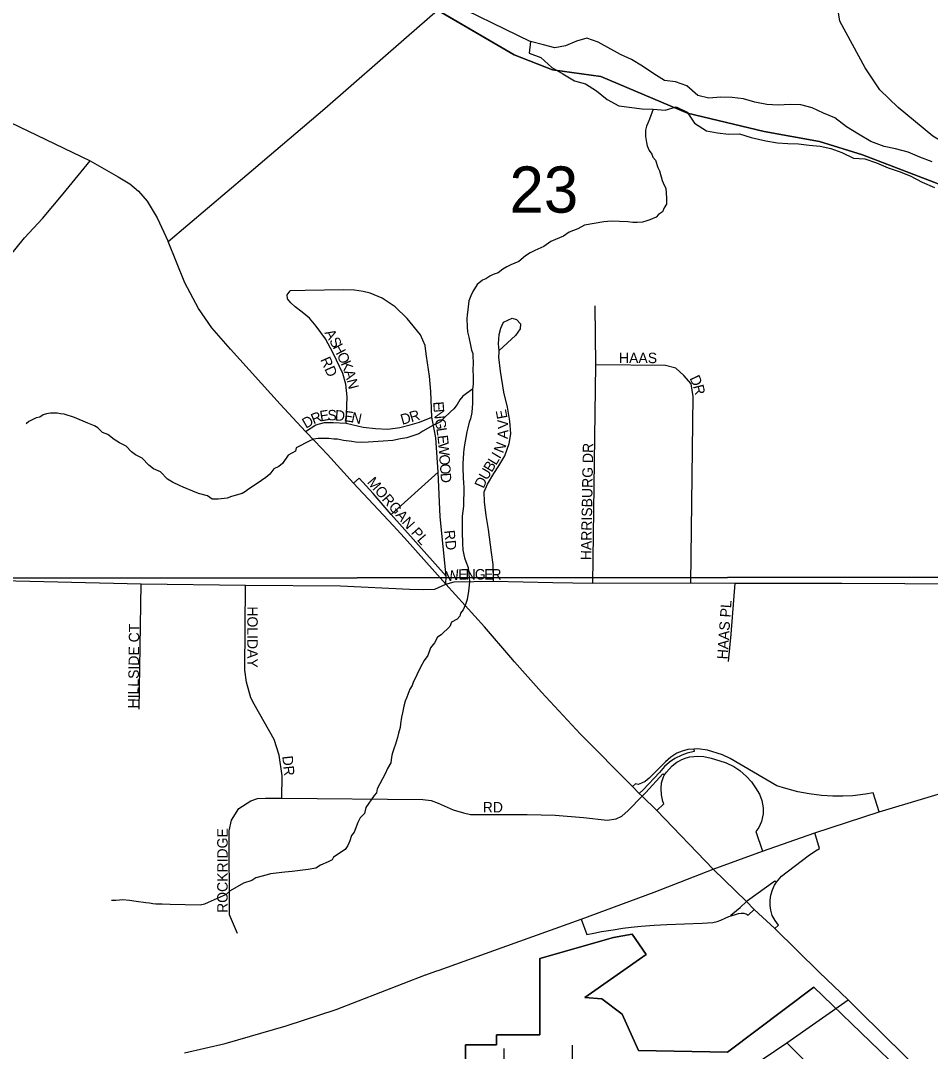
# Model space of a CAD drawing. Extents: x -209 to 4852, y 0 to 905.
# Drawn here: x 367.31 to 383.78, y 269.97 to 288.63 of the extents above; entities that cross this region are included whole.
import ezdxf

# ---------------------------------------------------------------- set-up
doc = ezdxf.new("R2010")
doc.units = 0
for name, color, linetype in [('GM_X_Airport_Location_Class_2', 7, 'Continuous'), ('GM_X_Airport_Location_Class_3', 7, 'Continuous'), ('GM_X_Corporation', 7, 'Continuous'), ('GM_X_County_Road', 7, 'Continuous'), ('GM_X_County_ROW', 7, 'Continuous'), ('GM_X_County_Subdivision_Text', 7, 'Continuous'), ('GM_X_Major_Lake', 7, 'Continuous'), ('GM_X_Minor_Lake_Text', 7, 'Continuous'), ('GM_X_Minor_River', 7, 'Continuous'), ('GM_X_Rail_Line', 7, 'Continuous'), ('GM_X_Rail_Line_Text', 7, 'Continuous'), ('GM_X_Township_Road_Text', 7, 'Continuous'), ('GM_X_US_Location', 7, 'Continuous')]:
    doc.layers.add(name, color=color, linetype=linetype)

msp = doc.modelspace()

# ---------------------------------------------------------------- linework, layer by layer
at = {"layer": 'GM_X_Airport_Location_Class_2'}
for points in [[(367.041, 284.247), (367.104, 284.359), (367.379, 284.704), (367.703, 285.054), (368.078, 285.498), (368.57, 286.095)], [(373.206, 281.346), (373.224, 281.827), (373.199, 282.052), (373.143, 282.249), (372.971, 282.617), (372.831, 282.877), (372.659, 283.101), (372.54, 283.251), (372.409, 283.355), (372.281, 283.455), (372.203, 283.523), (372.142, 283.596), (372.134, 283.67), (372.187, 283.742)], [(374.639, 282.698), (374.632, 282.752), (374.547, 282.944), (374.311, 283.242), (374.091, 283.451), (373.854, 283.608), (373.641, 283.698), (373.51, 283.731), (373.357, 283.753), (373.162, 283.759), (372.459, 283.748), (372.187, 283.742)], [(377.668, 278.453), (377.723, 282.403), (377.711, 283.474)], [(375.972, 282.633), (375.973, 282.663), (375.961, 282.784), (375.973, 282.953), (376.002, 283.069), (376.055, 283.175), (376.211, 283.25), (376.286, 283.225), (376.361, 283.147), (376.355, 283.056), (376.27, 282.934), (375.973, 282.663)], [(375.009, 278.433), (375.017, 278.576), (374.903, 279.654), (374.869, 280.46), (374.825, 281.082), (374.776, 281.366), (374.757, 281.457), (374.735, 281.919), (374.71, 282.2), (374.658, 282.558), (374.639, 282.698)], [(375.871, 278.485), (375.864, 278.789), (375.833, 279.004), (375.78, 279.423), (375.739, 279.676), (375.708, 279.923), (375.705, 280.107), (375.764, 280.245), (375.88, 280.435), (375.967, 280.573), (376.077, 280.757), (376.155, 280.979), (376.183, 281.157), (376.17, 281.382), (376.123, 281.635), (376.058, 281.907), (375.998, 282.291), (375.967, 282.544), (375.972, 282.633)], [(379.445, 278.46), (379.488, 281.831), (379.451, 282.062), (379.317, 282.208), (379.171, 282.342), (378.989, 282.391), (377.723, 282.403)], [(372.469, 281.198), (372.656, 281.315), (372.811, 281.359), (372.971, 281.358), (373.206, 281.346), (373.512, 281.277), (373.737, 281.252), (373.956, 281.241), (374.174, 281.268), (374.365, 281.315), (374.53, 281.365), (374.757, 281.457)], [(375.017, 278.576), (374.813, 278.801), (374.019, 279.695), (373.69, 280.074), (373.437, 280.351), (373.337, 280.262)], [(374.019, 279.695), (374.869, 280.46)], [(366.714, 278.504), (366.718, 278.504), (369.489, 278.438), (371.38, 278.415), (373.101, 278.401), (374.348, 278.345), (374.601, 278.336), (374.807, 278.345), (375.009, 278.433)], [(369.457, 276.172), (369.489, 278.438)], [(372.036, 274.557), (372.046, 274.963), (371.992, 275.335), (371.897, 275.622), (371.539, 276.261), (371.48, 276.375), (371.401, 276.657), (371.369, 276.877), (371.38, 278.415)], [(375.009, 278.433), (375.162, 278.477), (375.871, 278.485), (376.948, 278.466)], [(376.948, 278.466), (377.668, 278.453), (379.445, 278.46), (380.246, 278.449), (380.409, 278.45), (380.991, 278.449), (382.181, 278.449), (384.461, 278.437), (385.708, 278.435), (386.478, 278.437)], [(380.129, 277.031), (380.176, 277.528), (380.246, 278.449)], [(371.238, 272.107), (371.093, 272.449), (371.085, 273.966), (371.128, 274.163), (371.26, 274.371), (371.478, 274.513), (371.598, 274.554), (371.741, 274.557), (372.036, 274.557), (374.595, 274.535), (374.742, 274.518), (374.868, 274.469), (375.141, 274.349), (375.327, 274.294), (375.453, 274.264), (376.481, 274.264), (376.986, 274.25), (377.503, 274.207), (377.93, 274.163), (378.094, 274.185), (378.195, 274.234), (378.312, 274.338), (378.564, 274.595)], [(376.058, 269.566), (377.306, 269.552), (378.494, 269.542), (378.988, 269.535), (379.179, 269.522), (379.661, 269.42), (380.115, 269.461), (380.21, 269.493), (380.327, 269.548), (381.186, 270.131), (382.291, 270.908)], [(376.058, 270.024), (376.058, 269.566), (376.043, 266.655), (376.039, 265.976)], [(377.3, 266.702), (377.306, 269.552), (377.3, 270.086)], [(381.186, 270.131), (382.001, 269.307), (382.577, 268.74)]]:
    msp.add_lwpolyline(points, dxfattribs=at)
at = {"layer": 'GM_X_Corporation'}
for points in [[(359.101, 295.92), (359.22, 295.726), (359.989, 294.559), (360.498, 293.749), (360.741, 293.376), (360.976, 293.005), (361.061, 292.879), (361.234, 292.661), (361.398, 292.456), (361.814, 292.009), (362.465, 291.319), (363.235, 290.501), (363.961, 289.719), (364.692, 288.915), (364.928, 288.634), (365.294, 288.254), (365.884, 287.631), (366.349, 287.246), (366.697, 287.014), (367.127, 286.793), (368.57, 286.095)], [(369.983, 284.636), (371.408, 285.845), (372.818, 287.046), (374.298, 288.338), (374.86, 288.826), (375.008, 288.954)], [(368.57, 286.095), (369.076, 285.808), (369.284, 285.682), (369.441, 285.55), (369.6, 285.369), (369.782, 285.065), (369.983, 284.636)]]:
    msp.add_lwpolyline(points, dxfattribs=at)
at = {"layer": 'GM_X_County_Road'}
for points in [[(378.764, 287.034), (378.696, 286.848), (378.665, 286.78), (378.641, 286.727), (378.624, 286.651), (378.622, 286.537), (378.643, 286.43), (378.657, 286.369), (378.693, 286.285), (378.738, 286.216), (378.759, 286.162), (378.804, 286.108), (378.847, 285.978), (378.876, 285.917), (378.926, 285.741), (378.963, 285.657), (378.992, 285.603), (379.004, 285.421), (379.002, 285.314), (378.963, 285.246), (378.931, 285.171), (378.862, 285.127), (378.815, 285.074), (378.701, 285.031), (378.647, 285.009), (378.571, 284.987), (378.472, 284.981), (378.396, 284.983), (378.305, 284.992), (378.002, 285.005), (377.872, 284.992), (377.522, 284.93), (377.399, 284.864), (377.239, 284.806), (377.139, 284.731), (376.993, 284.673), (376.909, 284.637), (376.786, 284.548), (376.618, 284.475), (376.534, 284.43), (376.449, 284.379), (376.333, 284.274), (376.188, 284.216), (376.111, 284.18), (376.042, 284.135), (375.957, 284.068), (375.866, 284.039), (375.805, 284.01), (375.735, 283.958), (375.674, 283.936), (375.574, 283.855), (375.496, 283.734), (375.464, 283.651), (375.424, 283.561), (375.406, 283.401), (375.397, 283.31), (375.388, 283.234), (375.393, 283.09), (375.399, 282.999), (375.427, 282.907), (375.462, 282.731), (375.476, 282.67), (375.498, 282.609), (375.497, 282.541), (375.503, 282.457), (375.5, 282.29), (375.506, 282.214), (375.503, 282.054), (375.494, 281.963), (375.49, 281.773), (375.489, 281.697), (375.487, 281.629), (375.478, 281.538), (375.453, 281.424), (375.429, 281.364), (375.405, 281.265), (375.388, 281.19), (375.371, 281.091), (375.346, 280.955), (375.337, 280.871), (375.328, 280.81), (375.317, 280.613), (375.316, 280.537), (375.32, 280.362), (375.326, 280.263), (375.332, 280.187), (375.326, 279.845), (375.307, 279.663), (375.302, 279.382), (375.313, 279.169), (375.318, 279.047), (375.346, 278.91), (375.368, 278.841), (375.411, 278.734), (375.431, 278.551), (375.437, 278.475), (375.427, 278.361), (375.419, 278.308), (375.393, 278.156), (375.369, 278.081)], [(375.494, 281.963), (375.317, 281.837), (375.262, 281.77), (375.215, 281.687), (375.153, 281.604), (375.091, 281.552), (374.975, 281.44), (374.913, 281.373), (374.775, 281.307), (374.591, 281.204), (374.522, 281.152), (374.354, 281.101), (374.301, 281.08), (374.186, 281.066), (374.049, 281.031), (373.874, 281.019), (373.601, 281.001), (373.487, 280.995), (373.373, 281.005), (373.305, 281.014), (373.153, 281.032), (373.048, 281.056), (372.979, 281.057), (372.888, 281.067), (372.699, 281.07), (372.615, 281.056), (372.546, 281.027), (372.301, 280.902), (372.284, 280.842), (372.154, 280.768), (372.053, 280.618), (371.983, 280.566), (371.891, 280.522), (371.821, 280.424), (371.752, 280.365), (371.59, 280.254), (371.437, 280.15), (371.383, 280.113), (371.321, 280.076), (371.13, 280.018), (371.046, 279.99), (370.887, 279.97), (370.78, 279.971), (370.69, 280.034), (370.532, 280.075), (370.426, 280.115), (370.253, 280.186), (370.2, 280.21), (370.057, 280.281), (369.967, 280.336), (369.841, 280.467), (369.712, 280.523), (369.63, 280.585), (369.511, 280.716), (369.391, 280.772), (369.316, 280.826), (369.219, 280.934), (369.099, 280.99), (369.001, 281.052), (368.889, 281.145), (368.791, 281.178), (368.709, 281.263), (368.649, 281.302), (368.528, 281.35), (368.287, 281.453), (368.098, 281.509), (368.03, 281.518), (367.97, 281.527), (367.848, 281.529), (367.78, 281.515), (367.719, 281.501), (367.657, 281.456), (367.589, 281.442), (367.458, 281.376), (367.411, 281.337)], [(375.369, 278.081), (375.321, 277.967), (375.275, 277.907), (375.259, 277.855), (375.212, 277.802), (375.112, 277.743), (375.081, 277.668), (374.926, 277.518), (374.857, 277.474), (374.802, 277.369), (374.732, 277.279), (374.684, 277.143), (374.614, 277.053), (374.551, 276.932), (374.416, 276.653), (374.4, 276.6), (374.354, 276.533), (374.305, 276.389), (374.274, 276.314), (374.249, 276.223), (374.224, 276.102), (374.208, 276.026), (374.19, 275.905), (374.181, 275.836), (374.149, 275.738), (374.132, 275.655), (374.1, 275.534), (374.068, 275.451), (374.036, 275.36), (374.027, 275.299), (374.01, 275.201), (373.955, 275.095), (373.908, 274.997), (373.766, 274.726), (373.75, 274.658), (373.711, 274.606), (373.562, 274.388), (373.538, 274.282), (373.46, 274.2), (373.413, 274.117), (373.349, 273.943), (373.303, 273.883), (373.27, 273.785), (373.231, 273.702), (373.184, 273.627), (372.977, 273.493), (372.953, 273.441), (372.876, 273.404), (372.739, 273.346), (372.654, 273.294), (372.517, 273.266), (372.228, 273.233), (372.091, 273.22), (371.832, 273.187), (371.771, 273.173), (371.565, 273.116), (371.496, 273.071), (371.343, 273.021), (371.105, 272.881), (371.028, 272.814), (370.814, 272.719), (370.707, 272.667), (370.638, 272.638), (370.562, 272.624), (370.015, 272.634), (369.871, 272.637), (369.757, 272.639), (369.704, 272.647), (369.644, 272.656), (369.575, 272.665), (369.401, 272.69), (369.28, 272.708), (369.151, 272.718), (369.098, 272.711), (369.03, 272.705), (368.954, 272.706)]]:
    msp.add_lwpolyline(points, dxfattribs=at)
at = {"layer": 'GM_X_County_ROW'}
msp.add_lwpolyline([(390.832, 279.665), (390.717, 279.84), (389.88, 280.947), (388.914, 282.079), (387.709, 283.398), (386.607, 284.547), (385.584, 285.46), (384.962, 285.865), (383.83, 286.545), (383.202, 287.064), (382.866, 287.381), (382.6, 287.78), (382.145, 288.623), (382.083, 289.011)], dxfattribs=at)
at = {"layer": 'GM_X_County_Subdivision_Text'}
for points in [[(374.052, 279.497), (373.337, 280.262), (372.866, 280.779), (372.636, 281.022), (372.469, 281.198), (372.009, 281.694), (371.11, 282.69), (370.771, 283.071), (370.529, 283.422), (370.283, 283.886), (369.983, 284.636)], [(376.251, 277.029), (376.183, 277.105), (375.708, 277.658), (375.009, 278.433), (374.261, 279.273), (374.052, 279.497)], [(379.85, 273.272), (378.828, 274.334), (378.564, 274.595), (378.511, 274.645), (378.388, 274.769), (377.45, 275.718), (376.741, 276.477), (376.251, 277.029)], [(383.116, 270.095), (382.291, 270.908), (381.77, 271.411), (380.966, 272.199), (380.593, 272.542), (380.452, 272.688), (379.85, 273.272)], [(383.528, 269.688), (383.521, 269.695), (383.125, 270.086), (383.116, 270.095)]]:
    msp.add_lwpolyline(points, dxfattribs=at)
at = {"layer": 'GM_X_Major_Lake'}
msp.add_line((373.752, 289.621), (376.539, 288.257), dxfattribs=at)
for points in [[(383.815, 286.077), (383.589, 286.164), (383.378, 286.251), (383.151, 286.316), (382.947, 286.357), (382.706, 286.445), (382.48, 286.578), (382.263, 286.711), (382.053, 286.874), (381.85, 286.961), (381.639, 287.055), (381.435, 287.112), (381.245, 287.115), (381.025, 287.103), (380.821, 287.114), (380.601, 287.156), (380.397, 287.22), (380.193, 287.246), (379.988, 287.25), (379.768, 287.231), (379.572, 287.279), (379.37, 287.457), (379.166, 287.529), (378.969, 287.548), (378.774, 287.672), (378.572, 287.813), (378.369, 287.93), (378.173, 288.024), (377.767, 288.244), (377.563, 288.316), (377.373, 288.265), (377.174, 288.178), (376.984, 288.143), (376.78, 288.199), (376.539, 288.257)], [(376.539, 288.257), (376.52, 288.044)], [(376.52, 288.044), (376.731, 287.965), (376.925, 287.787), (377.128, 287.669), (377.338, 287.544), (377.535, 287.488), (377.737, 287.363), (377.932, 287.208), (378.143, 287.09), (378.566, 287.038), (378.764, 287.034), (378.983, 287.016), (379.181, 287.073), (379.377, 286.979), (379.51, 286.779), (379.728, 286.638), (379.925, 286.605), (380.129, 286.579), (380.326, 286.583), (380.538, 286.519), (380.802, 286.461), (381.014, 286.42), (381.203, 286.409), (381.393, 286.406), (381.59, 286.38), (381.787, 286.361), (381.983, 286.32), (382.179, 286.248), (382.39, 286.146), (382.595, 286.135), (382.806, 286.063), (383.017, 285.969), (383.22, 285.904), (383.416, 285.825), (383.634, 285.708), (383.86, 285.613)]]:
    msp.add_lwpolyline(points, dxfattribs=at)
at = {"layer": 'GM_X_Minor_Lake_Text'}
msp.add_lwpolyline([(367.283, 295.619), (368.159, 294.351), (368.732, 293.446), (370.241, 292.029), (372.113, 290.822), (372.777, 290.158), (374.86, 288.826), (376.248, 288.017), (376.942, 287.745), (377.818, 287.625), (379.387, 286.961), (380.775, 286.63), (381.772, 286.449), (382.556, 286.208), (384.126, 285.604), (384.941, 285.092), (385.816, 284.368), (386.661, 283.508), (387.356, 282.694), (388.05, 282), (390.832, 278.706), (390.832, 338.559), (362.726, 338.559)], dxfattribs=at)
at = {"layer": 'GM_X_Minor_River'}
for points in [[(366.855, 298.625), (386.92, 298.555), (386.82, 278.559), (366.685, 278.54)], [(366.685, 278.54), (386.82, 278.559), (386.662, 258.306), (366.643, 258.429)]]:
    msp.add_lwpolyline(points, close=True, dxfattribs=at)
at = {"layer": 'GM_X_Rail_Line'}
for points in [[(382.855, 274.31), (382.747, 274.653), (382.61, 274.629), (382.377, 274.603), (382.198, 274.594), (382.014, 274.595), (381.813, 274.607), (381.589, 274.636), (381.383, 274.676), (381.167, 274.732), (381.004, 274.785), (380.155, 275.275), (380.017, 275.344), (379.748, 275.429), (379.57, 275.45), (379.501, 275.445), (379.392, 275.438), (379.286, 275.41), (379.189, 275.374), (379.083, 275.299), (378.986, 275.215), (378.691, 274.921), (378.62, 274.858), (378.553, 274.829), (378.494, 274.809), (378.441, 274.818), (378.388, 274.769)], [(379.501, 275.445), (379.504, 275.402), (379.381, 275.374), (379.279, 275.338), (379.153, 275.274), (379.06, 275.21), (378.971, 275.132), (378.876, 275.023), (378.581, 274.708), (378.511, 274.645)], [(378.828, 274.334), (378.954, 274.458), (378.939, 274.496), (378.913, 274.618), (378.905, 274.731), (378.914, 274.837), (378.951, 274.946), (378.971, 274.979), (379.002, 275.028), (379.107, 275.146), (379.19, 275.208), (379.239, 275.236), (379.283, 275.256), (379.358, 275.286), (379.429, 275.306), (379.5, 275.316), (379.56, 275.32), (379.681, 275.311), (379.811, 275.282), (379.949, 275.243), (380.082, 275.201), (380.225, 275.129), (380.332, 275.057), (380.454, 274.95), (380.541, 274.852), (380.614, 274.748), (380.688, 274.634), (380.733, 274.515), (380.757, 274.384), (380.752, 274.273), (380.722, 274.139), (380.675, 274.03), (380.619, 273.955), (380.743, 273.598)], [(378.564, 274.595), (378.633, 274.659), (378.936, 275.002), (378.971, 274.979)], [(380.966, 272.199), (381.031, 272.257), (380.971, 272.343), (380.917, 272.437), (380.892, 272.529), (380.88, 272.615), (380.881, 272.71), (380.894, 272.8), (380.923, 272.897), (380.962, 272.981), (380.998, 273.041), (381.087, 273.144), (381.571, 273.516), (381.705, 273.606), (381.777, 273.65), (381.691, 273.93)], [(380.452, 272.688), (380.47, 272.705), (380.968, 273.06), (380.998, 273.041)], [(380.173, 272.428), (380.169, 272.441), (380.338, 272.579), (380.452, 272.688)], [(377.46, 272.367), (377.563, 272.09), (377.691, 272.117), (377.829, 272.143), (378.039, 272.178), (378.211, 272.203), (378.363, 272.222), (378.546, 272.241), (378.778, 272.259), (379.009, 272.271), (379.651, 272.298), (379.842, 272.31), (379.923, 272.327), (379.988, 272.349), (380.066, 272.387), (380.131, 272.417), (380.173, 272.428), (380.27, 272.456), (380.308, 272.469), (380.359, 272.477), (380.403, 272.475), (380.442, 272.464), (380.462, 272.455), (380.482, 272.441), (380.593, 272.542)]]:
    msp.add_lwpolyline(points, dxfattribs=at)
at = {"layer": 'GM_X_Rail_Line_Text'}
for points in [[(379.85, 273.272), (380.743, 273.598), (381.691, 273.93), (382.855, 274.31), (384.448, 274.788), (385.936, 275.215), (386.612, 275.395)], [(374.828, 271.426), (374.885, 271.447), (376.026, 271.856), (377.46, 272.367), (378.778, 272.86), (379.85, 273.272)], [(370.277, 269.948), (371.01, 270.115), (372.119, 270.44), (373.021, 270.732), (374.64, 271.359)], [(374.64, 271.359), (374.645, 271.36), (374.828, 271.426)]]:
    msp.add_lwpolyline(points, dxfattribs=at)
at = {"layer": 'GM_X_US_Location'}
for points in [[(390.832, 269.015), (390.832, 278.706), (388.05, 282), (387.356, 282.694), (386.661, 283.508), (385.816, 284.368), (384.941, 285.092), (384.126, 285.604), (382.556, 286.208), (381.772, 286.449), (380.775, 286.63), (379.387, 286.961), (377.818, 287.625), (376.942, 287.745), (376.248, 288.017), (374.799, 288.861), (372.777, 290.158), (372.113, 290.822), (370.241, 292.029), (368.732, 293.446), (368.159, 294.351), (367.283, 295.619)], [(375.367, 265.792), (375.367, 270.094), (375.925, 270.094), (375.925, 270.274), (376.711, 270.274), (376.711, 271.656), (378.046, 272.038), (378.385, 272.097), (378.635, 271.727), (377.523, 270.949), (377.833, 270.924), (378.201, 270.651), (378.495, 269.99), (380.106, 269.962), (381.675, 271.136), (383.375, 269.495)], [(383.375, 269.495), (381.675, 271.136), (380.106, 269.962), (378.495, 269.99), (378.201, 270.651), (377.833, 270.924), (377.523, 270.949), (378.635, 271.727), (378.385, 272.097), (378.046, 272.038), (376.711, 271.656), (376.711, 270.274), (375.925, 270.274), (375.925, 270.094), (375.367, 270.094), (375.367, 265.792)], [(383.375, 269.495), (381.675, 271.136), (380.106, 269.962), (378.495, 269.99), (378.201, 270.651), (377.833, 270.924), (377.523, 270.949), (378.635, 271.727), (378.385, 272.097), (378.046, 272.038), (376.711, 271.656), (376.711, 270.274), (375.925, 270.274), (375.925, 270.094), (375.367, 270.094), (375.367, 265.792)]]:
    msp.add_lwpolyline(points, dxfattribs=at)

# ---------------------------------------------------------------- texts
at = {"layer": 'GM_X_Airport_Location_Class_3'}
for s, height, rotation, p in [('A', 0.189, 299.6744, (372.807, 282.984)), ('S', 0.189, 299.6703, (372.89, 282.839)), ('H', 0.189, 297.7871, (372.955, 282.725)), ('RD', 0.1894, 293.9636, (372.732, 282.498)), ('O', 0.189, 294.6194, (373.031, 282.58)), ('HAAS', 0.1894, 0, (378.144, 282.434)), ('K', 0.189, 293.2502, (373.1, 282.429)), ('A', 0.189, 286.672, (373.164, 282.282)), ('N', 0.189, 284.1105, (373.211, 282.124)), ('D', 0.189, 295.3431, (379.417, 282.161)), ('R', 0.189, 283.8537, (379.485, 282.02)), ('E', 0.189, 9.1388, (372.741, 281.379)), ('S', 0.189, 359.6175, (372.864, 281.399)), ('D', 0.189, 355.603, (372.994, 281.398)), ('E', 0.189, 273.7178, (374.779, 281.733)), ('N', 0.189, 275.5276, (374.789, 281.594)), ('E', 0.189, 100.7629, (376.127, 281.442)), ('D', 0.189, 29.9889, (372.475, 281.245)), ('R', 0.189, 22.108, (372.613, 281.325)), ('E', 0.189, 351.2788, (373.157, 281.386)), ('N', 0.189, 348.2228, (373.286, 281.366)), ('D', 0.189, 15.7113, (374.218, 281.316)), ('R', 0.189, 17.0082, (374.383, 281.362)), ('G', 0.189, 279.5001, (374.807, 281.414)), ('V', 0.189, 93.546, (376.141, 281.25)), ('L', 0.189, 279.2468, (374.834, 281.25)), ('A', 0.189, 86.2207, (376.13, 281.057)), ('E', 0.189, 276.3251, (374.855, 281.121)), ('W', 0.189, 274.3923, (374.87, 280.99)), ('N', 0.189, 68.2462, (376.044, 280.79)), ('HARRISBURG DR', 0.18939, 88.9756, (377.641, 278.865)), ('O', 0.189, 274.3099, (374.886, 280.774)), ('B', 0.189, 58.8905, (375.839, 280.446)), ('L', 0.189, 58.898, (375.917, 280.574)), ('I', 0.189, 58.927, (375.986, 280.689)), ('O', 0.189, 274.3099, (374.899, 280.608)), ('U', 0.189, 59.6885, (375.756, 280.303)), ('MORGAN PL', 0.1894, 311.0559, (373.572, 280.271)), ('D', 0.189, 274.2881, (374.911, 280.441)), ('D', 0.189, 66.4369, (375.692, 280.155)), ('RD', 0.1894, 276.0066, (374.979, 279.402)), ('W', 0.189, 8.8791, (375.028, 278.481)), ('E', 0.189, 1.3659, (375.236, 278.514)), ('N', 0.189, 0, (375.368, 278.517)), ('G', 0.189, 0, (375.534, 278.517)), ('E', 0.189, 0, (375.701, 278.517)), ('R', 0.189, 0, (375.834, 278.517)), ('HAAS PL', 0.1894, 85.9872, (380.108, 277.067)), ('HOLIDAY', 0.1894, 270, (371.413, 278.031)), ('HILLSIDE CT', 0.18939, 89.3183, (369.442, 276.182)), ('DR', 0.1894, 276.0054, (372.046, 275.318)), ('RD', 0.1894, 0, (375.677, 274.3)), ('ROCKRIDGE', 0.1894, 90, (371.058, 272.481))]:
    msp.add_text(s, height=height, rotation=rotation, dxfattribs=at).set_placement(p)
at = {"layer": 'GM_X_Township_Road_Text'}
msp.add_text('23', height=0.8371, rotation=0, dxfattribs=at).set_placement((376.161, 285.158))

doc.saveas('drawing.dxf')
